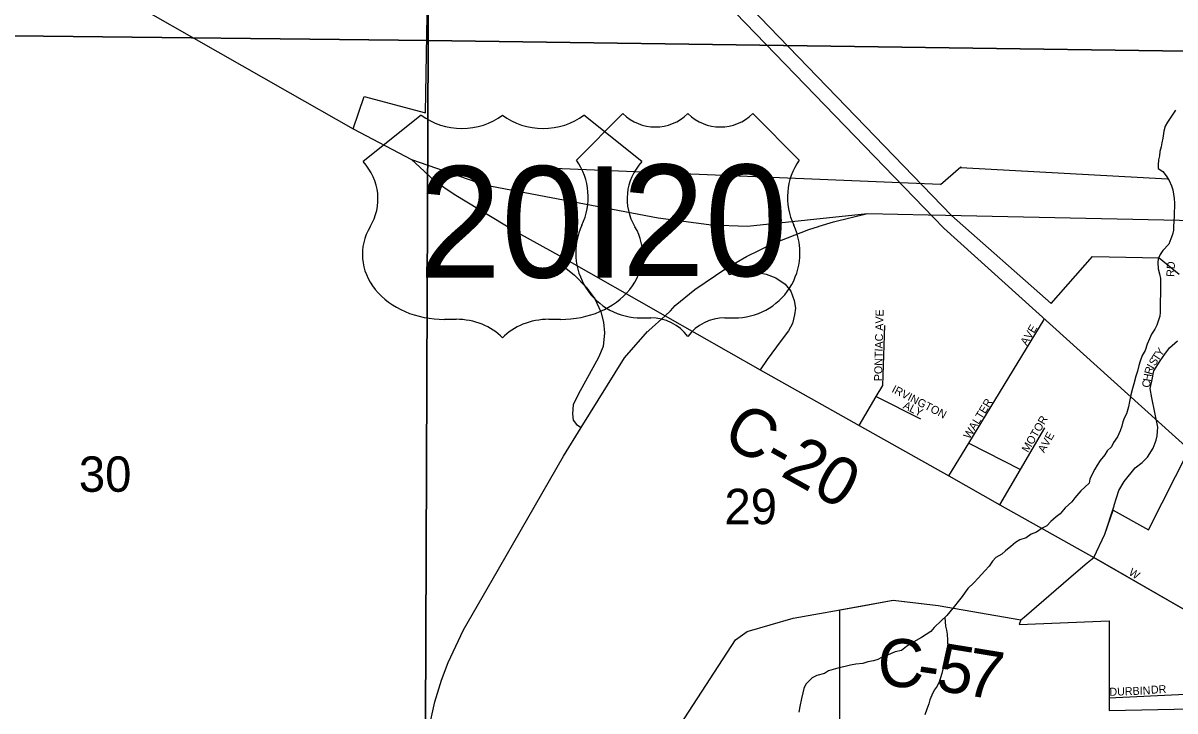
# Model space of a CAD drawing. Extents: x 1588073 to 2013523, y 1090242 to 1357120.
# Drawn here: x 1783199 to 1790397, y 1224591 to 1228891 of the extents above; entities that cross this region are included whole.
import ezdxf

# ---------------------------------------------------------------- set-up
doc = ezdxf.new("R2010")
doc.units = 0
for name, color, linetype in [('GM_X_City_Street', 7, 'Continuous'), ('GM_X_City_Street_Text', 7, 'Continuous'), ('GM_X_Corporation', 7, 'Continuous'), ('GM_X_County_Road', 7, 'Continuous'), ('GM_X_County_Road_Text', 7, 'Continuous'), ('GM_X_Interchange_Ramps', 7, 'Continuous'), ('GM_X_Minor_River', 7, 'Continuous'), ('GM_X_Section', 7, 'Continuous'), ('GM_X_Section_Text', 7, 'Continuous'), ('GM_X_Township_Road', 7, 'Continuous'), ('GM_X_Township_Subdivision', 7, 'Continuous'), ('GM_X_Township_Subdivision_Text', 7, 'Continuous'), ('GM_X_US_Location', 7, 'Continuous'), ('GM_X_US_Route', 7, 'Continuous'), ('GM_X_US_Shield', 7, 'Continuous')]:
    doc.layers.add(name, color=color, linetype=linetype)

msp = doc.modelspace()

# ---------------------------------------------------------------- linework, layer by layer
at = {"layer": 'GM_X_City_Street'}
for points in [[(1790253.8, 1226548.5), (1790242.6, 1226606.1), (1790252.5, 1226652.5), (1790266.1, 1226716.2), (1790305, 1226779.9), (1790333.7, 1226819.7), (1790362.3, 1226859.5), (1790413, 1226903.1)], [(1789889.5, 1225549.1), (1790459.9, 1225222.2), (1790975.7, 1224926.6)]]:
    msp.add_lwpolyline(points, dxfattribs=at)
at = {"layer": 'GM_X_Corporation'}
for points in [[(1790494.7, 1225202.2), (1789889.5, 1225549.1), (1789959.6, 1225694.7), (1790011.6, 1225844.6), (1790232.2, 1225722.4), (1790486.8, 1226225), (1788952.8, 1227608.3), (1786847.3, 1229788.7), (1785934.3, 1229788.7), (1785943.9, 1230338.6), (1785744.8, 1230335.6), (1785747.8, 1231084), (1786220.1, 1230599.6), (1786232.4, 1231304.5), (1788385.4, 1231304.5), (1788359, 1229795.7), (1786966, 1229795.8), (1789001.4, 1227688.1), (1789623.1, 1227137.8), (1789882, 1227431.1), (1790299.3, 1227422.5), (1790422.7, 1227319.8)], [(1790938, 1221768.4), (1790146.7, 1221772.1), (1790148.2, 1220750.8), (1787093.7, 1220794.7), (1787093.4, 1221795.3), (1785760.9, 1221771.7), (1785760.6, 1222736.3), (1785795.6, 1223137), (1785795.5, 1223405.2), (1786322.7, 1223414.5), (1786530.5, 1223490.2), (1787160.4, 1223719.7), (1787177.1, 1223583.6), (1787404.2, 1223271.2), (1787632.8, 1223456.4), (1788304.4, 1223468.3), (1788303.9, 1225222.5), (1788636.8, 1225282.9), (1788917.1, 1225249.5), (1789435.1, 1225159.2), (1789423.4, 1225132), (1789985.6, 1225154.5), (1789985.7, 1224594.2), (1790494.9, 1224603.2)]]:
    msp.add_lwpolyline(points, dxfattribs=at)
at = {"layer": 'GM_X_County_Road'}
for points in [[(1787806.2, 1226722.9), (1788423.6, 1226375), (1788983.9, 1226059.4)], [(1790017.8, 1225876.1), (1790047.5, 1225968.5), (1790080.3, 1226024.3), (1790149.6, 1226109.8), (1790192.2, 1226143.3), (1790224.7, 1226177.1), (1790261.6, 1226232.8), (1790280.3, 1226282.8), (1790286.7, 1226310.7), (1790289.4, 1226364.9), (1790253.8, 1226548.5)], [(1788983.9, 1226059.4), (1789303.4, 1225879.3), (1789889.5, 1225549.1)], [(1789889.5, 1225549.1), (1789959.6, 1225694.7), (1790017, 1225873.5), (1790017.8, 1225876.1)], [(1789455.1, 1225176.6), (1789777.9, 1225456.1), (1789849.5, 1225515.8)], [(1789849.5, 1225515.8), (1789849.6, 1225515.9), (1789889.5, 1225549.1)], [(1788434.2, 1225246.2), (1788636.8, 1225282.9), (1788740.6, 1225270.5), (1788742.3, 1225270.3)], [(1785769.3, 1223789), (1786047.1, 1223692.3), (1786356.6, 1223746.9), (1786916.1, 1224059.3), (1787106.4, 1224193.5), (1787333.8, 1224547.9), (1787651.1, 1225035.7), (1787724, 1225087), (1788011.8, 1225169.9), (1788433.6, 1225246.1), (1788434.2, 1225246.2)], [(1788742.3, 1225270.3), (1788917.1, 1225249.6), (1789435.1, 1225159.2), (1789454.8, 1225176.3), (1789455.1, 1225176.6)]]:
    msp.add_lwpolyline(points, dxfattribs=at)
at = {"layer": 'GM_X_Interchange_Ramps'}
for points in [[(1786567.1, 1227426.5), (1786548.2, 1227392.3), (1786645.8, 1227313.5), (1786717.7, 1227239.6), (1786771.3, 1227166.6), (1786810.5, 1227085.2), (1786826.6, 1227021.6), (1786833.3, 1226953.8), (1786823.5, 1226869.3), (1786795.9, 1226799.6), (1786667.7, 1226568.7), (1786635.7, 1226503.8), (1786631.9, 1226446.8), (1786637.1, 1226407.4), (1786658.1, 1226380.1), (1786686.5, 1226362.4)], [(1787590, 1227355.2), (1787611.3, 1227319), (1787691.1, 1227332.5), (1787770.7, 1227334.8), (1787842.9, 1227320.1), (1787903.6, 1227297.6), (1787961.6, 1227257.7), (1787996.3, 1227214.3), (1788018.3, 1227156.9), (1788027, 1227109.3), (1788019.2, 1227066.3), (1788008.2, 1227013.3), (1787982.6, 1226967.1), (1787937, 1226905.8), (1787848.8, 1226787.6), (1787806.2, 1226722.9)]]:
    msp.add_lwpolyline(points, dxfattribs=at)
at = {"layer": 'GM_X_Minor_River'}
for p, q in [((1786518.8, 1227983.2), (1788932.1, 1227882.6)), ((1788932, 1227880.6), (1789059.9, 1227991)), ((1789059.9, 1227991), (1789059.9, 1227987)), ((1789059.9, 1227987), (1790351.4, 1227917.4)), ((1788932.1, 1227882.6), (1788932, 1227880.6))]:
    msp.add_line(p, q, dxfattribs=at)
for points in [[(1790400.6, 1228346.3), (1790384.3, 1228320.4), (1790349.8, 1228270.6), (1790335.5, 1228246.7), (1790327.1, 1228214.7), (1790320.7, 1228170.6), (1790314.4, 1228142.6), (1790310.1, 1228116.6), (1790301.8, 1228086.6), (1790301.6, 1228060.6), (1790295.3, 1228034.6), (1790293, 1228004.5), (1790292.7, 1227980.5), (1790320.6, 1227962.2), (1790342.4, 1227935.9), (1790360.2, 1227905.6), (1790375.9, 1227873.4), (1790383.6, 1227847.3), (1790387.4, 1227821.2), (1790393.1, 1227793.1), (1790394.9, 1227765), (1790394.6, 1227736.9), (1790392.3, 1227712.9), (1790392.1, 1227686.8), (1790389.7, 1227648.8), (1790387.4, 1227620.7), (1790389.2, 1227596.6), (1790382.9, 1227568.6), (1790370.6, 1227540.7), (1790358.2, 1227508.7), (1790321.7, 1227469), (1790305.5, 1227443.1), (1790293.2, 1227417.2), (1790290.9, 1227393.1), (1790292.5, 1227355), (1790300.3, 1227322.9), (1790308, 1227292.7), (1790306.9, 1227186.5), (1790304.6, 1227160.4)], [(1790304.6, 1227160.4), (1790304.2, 1227114.3), (1790305.9, 1227084.3), (1790303.6, 1227058.2), (1790293.3, 1227026.2), (1790285, 1227002.3), (1790270.7, 1226976.3), (1790250.4, 1226946.5), (1790238.1, 1226916.5), (1790223.7, 1226882.6), (1790211.3, 1226844.6), (1790192.9, 1226812.7), (1790180.6, 1226776.8), (1790172.3, 1226750.8), (1790163.9, 1226714.8), (1790153.6, 1226682.8), (1790141.1, 1226634.8), (1790132.8, 1226606.8), (1790122.3, 1226566.8), (1790113.9, 1226524.8), (1790107.5, 1226490.8), (1790095.1, 1226448.8), (1790082.8, 1226424.9), (1790072.5, 1226396.9), (1790064.3, 1226371), (1790053.9, 1226341), (1790037.5, 1226303.1), (1790013.1, 1226269.2), (1790000.8, 1226241.3), (1789974.5, 1226215.5), (1789958.2, 1226191.6), (1789929.8, 1226155.8), (1789911.5, 1226125.9), (1789897.2, 1226102), (1789882.9, 1226074.1), (1789864.5, 1226040.2), (1789860.2, 1226014.1), (1789809.6, 1225966.5), (1789771.1, 1225922.8), (1789752.8, 1225896.9), (1789710.4, 1225861.2), (1789679.9, 1225823.5), (1789655.7, 1225803.6), (1789621.3, 1225773.9), (1789597, 1225748.1), (1789566.7, 1225732.4), (1789532.4, 1225708.6), (1789498.2, 1225694.9), (1789467.9, 1225673.2), (1789427.7, 1225659.6), (1789401.5, 1225643.8), (1789371.1, 1225618), (1789338.8, 1225592.3), (1789314.5, 1225570.5), (1789278.3, 1225550.8), (1789258, 1225526.9), (1789235.6, 1225495.1), (1789209.3, 1225467.2), (1789166.7, 1225419.6), (1789140.4, 1225391.8), (1789103.9, 1225356), (1789085.6, 1225332.1), (1789067.3, 1225306.3), (1789043, 1225274.4), (1789020.6, 1225246.6), (1788990.2, 1225210.8), (1788971.9, 1225186.9), (1788935.5, 1225153.2), (1788893, 1225111.5), (1788870.7, 1225087.7), (1788842.5, 1225067.9), (1788814.2, 1225050.2), (1788751.7, 1225014.7), (1788719.4, 1224993), (1788689.1, 1224969.2), (1788648.9, 1224959.6), (1788590.5, 1224934.1), (1788564.4, 1224924.3), (1788540.2, 1224912.5), (1788514, 1224904.8), (1788477.9, 1224897.1), (1788447.7, 1224887.4), (1788403.6, 1224883.8), (1788369.4, 1224876.1), (1788345.3, 1224870.3), (1788317.2, 1224864.6), (1788291.1, 1224858.8), (1788260.9, 1224849.1), (1788232.8, 1224841.4), (1788206.5, 1224825.6), (1788158.3, 1224812.1), (1788130.1, 1224798.3), (1788089.6, 1224758.6), (1788077.3, 1224730.6), (1788071, 1224704.7), (1788062.6, 1224668.6), (1788054.1, 1224618.6), (1788047.8, 1224582.6)], [(1788959.3, 1225175.2), (1788963.3, 1225120.9), (1788969, 1225094.7), (1788974.8, 1225070.6), (1788976.4, 1225032.5), (1788977.9, 1224982.4), (1788967.5, 1224940.4), (1788961.2, 1224916.4), (1788952.9, 1224888.4), (1788946.6, 1224852.4), (1788940.3, 1224824.4), (1788925.8, 1224776.4), (1788911.4, 1224744.5), (1788893.1, 1224720.6), (1788878.8, 1224688.7), (1788866.5, 1224660.7), (1788858.2, 1224634.8), (1788845.9, 1224602.8), (1788833.5, 1224566.8)]]:
    msp.add_lwpolyline(points, dxfattribs=at)
at = {"layer": 'GM_X_Section'}
for points in [[(1780754.9, 1234157.3), (1785757.6, 1234139.3), (1785731.5, 1228782.2), (1780549, 1228839.4), (1780748.6, 1234119.3)], [(1785757.6, 1234139.3), (1791128.3, 1234074.3), (1791058, 1228706), (1785731.5, 1228782.2)], [(1780549, 1228839.4), (1785731.5, 1228782.2), (1785709.2, 1223453.4), (1780320.7, 1223516.2), (1780325.3, 1223590.2)], [(1785731.5, 1228782.2), (1791058, 1228706), (1790931.8, 1223403.9), (1785709.2, 1223453.4)]]:
    msp.add_lwpolyline(points, close=True, dxfattribs=at)
at = {"layer": 'GM_X_Township_Road'}
msp.add_lwpolyline([(1785261.6, 1228228.4), (1785331.2, 1228430.8), (1785712.8, 1228330.1), (1785745.5, 1230159.2), (1785745.5, 1230484.9)], dxfattribs=at)
at = {"layer": 'GM_X_Township_Subdivision'}
for points in [[(1788983.9, 1226059.4), (1789108.5, 1226263.6), (1789580.7, 1227037)], [(1788423.6, 1226375), (1788530.8, 1226556.1), (1788571.2, 1226624.4), (1788585, 1226999.7)], [(1788530.8, 1226556.1), (1788806.5, 1226416.5)], [(1789303.4, 1225879.3), (1789432, 1226099.8), (1789583.7, 1226360.4)], [(1789108.5, 1226263.6), (1789432, 1226099.8)], [(1789983.6, 1224672.7), (1790463.4, 1224695.5)]]:
    msp.add_lwpolyline(points, dxfattribs=at)
at = {"layer": 'GM_X_US_Route'}
for points in [[(1783394.5, 1229294.4), (1784851.7, 1228462.4)], [(1784851.7, 1228462.4), (1784851.7, 1228462.4), (1785261.6, 1228228.4), (1785625.9, 1228038.3), (1786081.9, 1227878.9), (1787167, 1227673.1), (1787484.8, 1227630.5), (1787494.8, 1227630.1)], [(1785625.9, 1228038.3), (1785677.7, 1227988.7), (1785770.1, 1227904.5), (1785893.5, 1227821.5), (1786289.5, 1227581.9), (1786567.1, 1227426.5), (1787210.7, 1227061.1), (1787806.2, 1226722.9)], [(1787494.8, 1227630.1), (1787726.7, 1227621), (1788476.9, 1227700.6)], [(1788168.9, 1227618.1), (1788174.6, 1227619.8), (1788264.5, 1227647), (1788476.9, 1227700.6)], [(1788476.9, 1227700.6), (1788476.9, 1227700.6), (1788855.9, 1227692.4)], [(1788855.9, 1227692.4), (1788964.2, 1227690.1)], [(1788964.2, 1227690.1), (1790426.1, 1227658.6), (1793553.6, 1227591.2), (1793695.2, 1227588.2)], [(1787102.2, 1226962.7), (1787108.7, 1226968.6), (1787210.7, 1227061.1), (1787245.1, 1227092.2), (1787273.4, 1227125), (1787396, 1227224), (1787590, 1227355.2), (1787719.3, 1227431.4), (1787891, 1227515.4), (1788109.8, 1227600.2), (1788168.9, 1227618.1)], [(1786686.5, 1226362.4), (1786957.7, 1226798.7), (1787100.9, 1226961.6), (1787102.2, 1226962.7)], [(1785684.8, 1221799.5), (1785719.3, 1223806.4), (1785729, 1224371.7), (1785732.4, 1224468.3), (1785772, 1224647.1), (1785813.4, 1224782.9), (1785854.8, 1224893.5), (1785950.5, 1225096.9), (1786129.6, 1225407.3), (1786575.3, 1226183.6), (1786686.5, 1226362.4)]]:
    msp.add_lwpolyline(points, dxfattribs=at)
at = {"layer": 'GM_X_US_Shield'}
for p, q in [((1785687.6, 1228314.7), (1785325, 1228024.6)), ((1786947.2, 1228324.1), (1786657.2, 1228034)), ((1787065.3, 1228024.6), (1786702.7, 1228314.7)), ((1788049.3, 1228034), (1787759.3, 1228324.1)), ((1785832.6, 1227038.5), (1785905.1, 1227038.5)), ((1786485.2, 1227038.5), (1786557.7, 1227038.5)), ((1787063.2, 1227047.9), (1787121.2, 1227047.9)), ((1787585.3, 1227047.9), (1787643.3, 1227047.9))]:
    msp.add_line(p, q, dxfattribs=at)
for centre, radius, start, end in [((1787150.2, 1228531.2), 290, 225.573, 314.427), ((1787556.3, 1228531.2), 290, 225.573, 314.427), ((1786324.5, 1227801.1), 406.1, 334.54712, 35.00093), ((1788382, 1227801.1), 406.1, 144.99907, 205.45288), ((1787058.7, 1227453.9), 406.1, 154.83192, 270.63826), ((1787647.8, 1227453.9), 406.1, 269.36174, 25.16808), ((1787121.2, 1226757.9), 290, 36.8699, 90), ((1787585.3, 1226757.9), 290, 90, 143.1301)]:
    msp.add_arc(centre, radius, start, end, dxfattribs=at)
for centre, major_axis, start_param, end_param in [((1785941.4, 1228521.8), (-362.5, 0), 0.795399, 2.346194), ((1786448.9, 1228521.8), (-362.5, 0), 0.795399, 2.346194), ((1784909.3, 1227791.7), (507.6, 0), 5.838949, 6.894067), ((1787481, 1227791.7), (-507.6, 0), 5.672304, 6.727422), ((1785826.9, 1227444.5), (507.6, 0), 2.702327, 4.723529), ((1786563.4, 1227444.5), (-507.6, 0), 1.559657, 3.580859), ((1785905.1, 1226748.5), (-362.5, 0), 3.785094, 4.712389), ((1786485.2, 1226748.5), (-362.5, 0), 4.712389, 5.639684)]:
    msp.add_ellipse(centre, major_axis=major_axis, ratio=0.8, start_param=start_param, end_param=end_param, dxfattribs=at)

# ---------------------------------------------------------------- texts
at = {"layer": 'GM_X_City_Street_Text'}
for s, rotation, p in [('RD', 86.98841, (1790393.1, 1227302.7)), ('Y', 53.3443, (1790310.1, 1226801.6)), ('S', 57.26477, (1790272.3, 1226743.3)), ('T', 56.77222, (1790291.3, 1226772.8)), ('R', 74.08462, (1790252.5, 1226689.4)), ('I', 61.18729, (1790262.2, 1226724.8)), ('C', 80.60952, (1790239.2, 1226608.4)), ('H', 80.62691, (1790245.6, 1226647.5)), ('W', 327.52367, (1790103.9, 1225444.5))]:
    msp.add_text(s, height=50, rotation=rotation, dxfattribs=at).set_placement(p)
at = {"layer": 'GM_X_County_Road_Text'}
for s, rotation, p in [('C-20', 330.67929, (1787555.6, 1226271.3)), ('C', 359.6663, (1788539.3, 1224740.4)), ('5', 350.82, (1788895.3, 1224721.7)), ('7', 350.63521, (1789077.5, 1224692.3)), ('-', 351.48352, (1788774.4, 1224739.8))]:
    msp.add_text(s, height=300, rotation=rotation, dxfattribs=at).set_placement(p)
at = {"layer": 'GM_X_Section_Text'}
for s, p in [('30', (1783547.3, 1225960.5)), ('29', (1787582, 1225758.1))]:
    msp.add_text(s, height=221, rotation=0.00001, dxfattribs=at).set_placement(p)
at = {"layer": 'GM_X_Township_Subdivision_Text'}
for s, rotation, p in [('PONTIAC AVE', 88.75535, (1788567, 1226651.2)), ('AVE', 59.03238, (1789470.4, 1226871.4)), ('IRVINGTON', 332.76265, (1788623.1, 1226586)), ('ALY', 333.43495, (1788693.3, 1226484.3)), ('WALTER', 58.52408, (1789114, 1226286.3)), ('MOTOR', 59.82833, (1789479.1, 1226202.5)), ('AVE', 60.7509, (1789580.5, 1226200)), ('DURBIN', 2.16189, (1789988.5, 1224684.8)), ('DR', 3.01158, (1790248, 1224698))]:
    msp.add_text(s, height=50, rotation=rotation, dxfattribs=at).set_placement(p)
at = {"layer": 'GM_X_US_Location'}
for s, p in [('/', (1787352.9, 1227651.5)), ('0', (1787352.9, 1227651.5)), ('/', (1786195.7, 1227647.1)), ('0', (1786195.7, 1227647.1))]:
    msp.add_text(s, height=1, dxfattribs=at).set_placement(p)
for s, p in [('20I', (1785940.9, 1227440.1)), ('20', (1787146.5, 1227444.5))]:
    msp.add_text(s, height=1, rotation=0.00001, dxfattribs=at).set_placement(p)
at = {"layer": 'GM_X_US_Shield'}
for s, p in [('20', (1786941.7, 1227308.9)), ('20I', (1785669.2, 1227299.5))]:
    msp.add_text(s, height=696.1, dxfattribs=at).set_placement(p)

doc.saveas('drawing.dxf')
